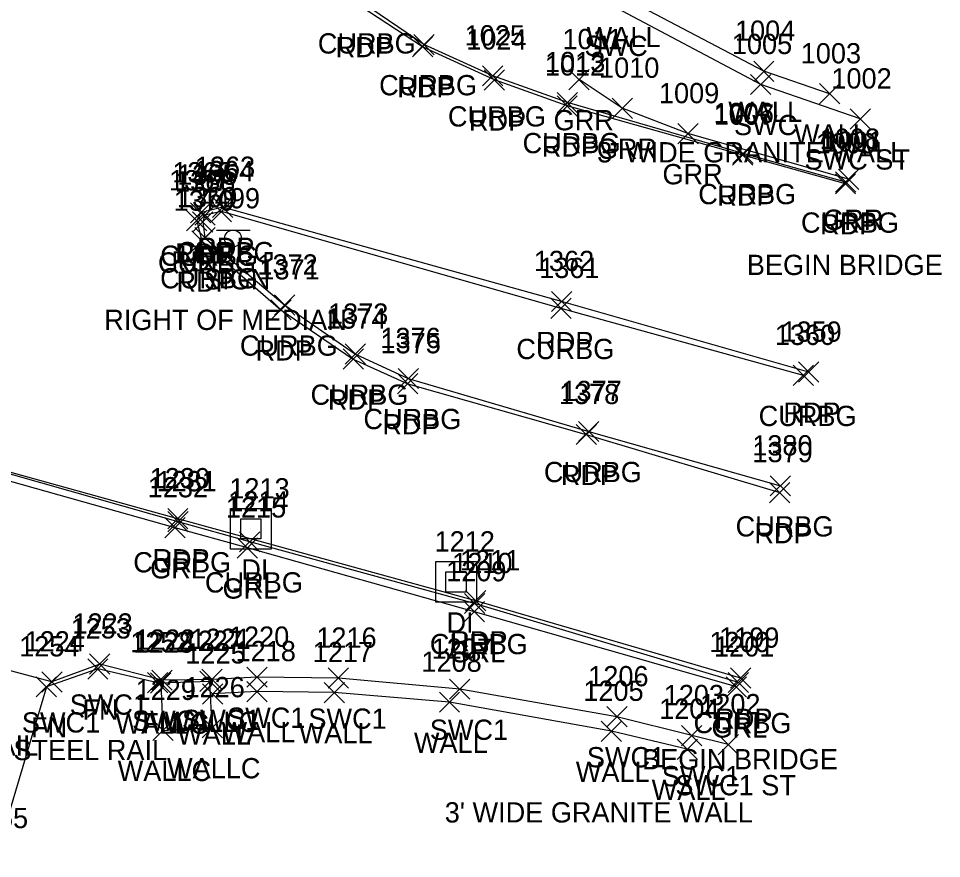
# Model space of a CAD drawing. Extents: x 1690689 to 1696275, y 438760 to 444007.
# Drawn here: x 1693096.4 to 1693187.5, y 438764.8 to 438847.7 of the extents above; entities that cross this region are included whole.
import ezdxf

# ---------------------------------------------------------------- set-up
doc = ezdxf.new("R2010")
doc.units = 0
for name, color, linetype in [('D_A', 7, 'Continuous'), ('D_I', 7, 'Continuous'), ('DS', 7, 'Continuous'), ('L_A', 7, 'Continuous'), ('L_C', 7, 'Continuous'), ('L_I', 7, 'Continuous'), ('L_TIC', 7, 'Continuous'), ('LFNC', 7, 'Continuous'), ('LW', 7, 'Continuous'), ('P_A', 7, 'Continuous'), ('P_C', 7, 'Continuous'), ('P_I', 7, 'Continuous'), ('P_TIC', 7, 'Continuous'), ('PET', 7, 'Continuous'), ('R_A', 7, 'Continuous'), ('R_I', 7, 'Continuous'), ('R_TIC', 7, 'Continuous'), ('RC', 7, 'Continuous'), ('RGR', 7, 'Continuous'), ('RSW', 7, 'Continuous'), ('S_A', 7, 'Continuous'), ('S_C', 7, 'Continuous'), ('S_I', 7, 'Continuous'), ('SSGN', 7, 'Continuous')]:
    doc.layers.add(name, color=color, linetype=linetype)

msp = doc.modelspace()

# ---------------------------------------------------------------- linework, layer by layer
at = {"layer": 'DS'}
for p, q in [((1693117.348, 438799.301), (1693121.348, 438799.301)), ((1693117.348, 438795.301), (1693117.348, 438799.301)), ((1693121.348, 438799.301), (1693121.348, 438795.301)), ((1693118.348, 438796.301), (1693118.348, 438798.301)), ((1693118.348, 438798.301), (1693120.348, 438798.301)), ((1693120.348, 438798.301), (1693120.348, 438796.301)), ((1693119.353, 438797.302), (1693119.353, 438797.302)), ((1693119.353, 438797.302), (1693119.353, 438797.302)), ((1693120.348, 438796.301), (1693118.348, 438796.301)), ((1693121.348, 438795.301), (1693117.348, 438795.301)), ((1693137.59, 438794.063), (1693141.59, 438794.063)), ((1693137.59, 438790.063), (1693137.59, 438794.063)), ((1693141.59, 438794.063), (1693141.59, 438790.063)), ((1693138.59, 438791.063), (1693138.59, 438793.063)), ((1693138.59, 438793.063), (1693140.59, 438793.063)), ((1693140.59, 438793.063), (1693140.59, 438791.063)), ((1693139.595, 438792.065), (1693139.595, 438792.065)), ((1693139.595, 438792.065), (1693139.595, 438792.065)), ((1693140.59, 438791.063), (1693138.59, 438791.063)), ((1693141.59, 438790.063), (1693137.59, 438790.063))]:
    msp.add_line(p, q, dxfattribs=at)
at = {"layer": 'L_TIC'}
for points in [[(1693168.95, 438841.46), (1693170.95, 438843.46)], [(1693170.95, 438841.46), (1693168.95, 438843.46)], [(1693175.439, 438839.232), (1693177.439, 438841.232)], [(1693177.439, 438839.232), (1693175.439, 438841.232)], [(1693103.258, 438782.476), (1693105.258, 438784.476)], [(1693105.258, 438782.476), (1693103.258, 438784.476)], [(1693109.146, 438781.122), (1693111.146, 438783.122)], [(1693111.146, 438781.122), (1693109.146, 438783.122)], [(1693109.459, 438781.081), (1693111.459, 438783.081)], [(1693111.459, 438781.081), (1693109.459, 438783.081)], [(1693114.306, 438781.254), (1693116.306, 438783.254)], [(1693116.306, 438781.254), (1693114.306, 438783.254)], [(1693098.184, 438780.712), (1693100.184, 438782.712)], [(1693100.184, 438780.712), (1693098.184, 438782.712)], [(1693114.581, 438780.013), (1693116.581, 438782.013)], [(1693116.581, 438780.013), (1693114.581, 438782.013)], [(1693118.968, 438780.242), (1693120.968, 438782.242)], [(1693120.968, 438780.242), (1693118.968, 438782.242)], [(1693126.581, 438780.148), (1693128.581, 438782.148)], [(1693128.581, 438780.148), (1693126.581, 438782.148)], [(1693137.944, 438779.198), (1693139.944, 438781.198)], [(1693139.944, 438779.198), (1693137.944, 438781.198)], [(1693109.68, 438776.414), (1693111.68, 438778.414)], [(1693111.68, 438776.414), (1693109.68, 438778.414)], [(1693114.548, 438776.683), (1693116.548, 438778.683)], [(1693116.548, 438776.683), (1693114.548, 438778.683)], [(1693153.914, 438776.324), (1693155.914, 438778.324)], [(1693155.914, 438776.324), (1693153.914, 438778.324)], [(1693161.395, 438774.55), (1693163.395, 438776.55)], [(1693163.395, 438774.55), (1693161.395, 438776.55)]]:
    msp.add_lwpolyline(points, dxfattribs=at)
at = {"layer": 'LFNC'}
msp.add_lwpolyline([(1693110.146, 438782.122), (1693104.258, 438783.476), (1693099.184, 438781.712), (1693094.123, 438764.767)], dxfattribs=at)
at = {"layer": 'LW'}
for points in [[(1693176.439, 438840.232), (1693169.95, 438842.46), (1693155.984, 438849.838), (1693140.477, 438863.014), (1693137.545, 438865.859)], [(1693115.548, 438777.683), (1693115.306, 438782.254), (1693110.459, 438782.081), (1693110.68, 438777.414)], [(1693162.395, 438775.55), (1693154.914, 438777.324), (1693138.944, 438780.198), (1693127.581, 438781.148), (1693119.968, 438781.242), (1693115.581, 438781.013)], [(1693110.68, 438777.414), (1693115.548, 438777.683)]]:
    msp.add_lwpolyline(points, dxfattribs=at)
at = {"layer": 'P_TIC'}
for points in [[(1693135.289, 438843.874), (1693137.289, 438845.874)], [(1693137.289, 438843.874), (1693135.289, 438845.874)], [(1693142.37, 438840.6), (1693144.37, 438842.6)], [(1693144.37, 438840.6), (1693142.37, 438842.6)], [(1693149.55, 438838.032), (1693151.55, 438840.032)], [(1693151.55, 438838.032), (1693149.55, 438840.032)], [(1693166.863, 438833.182), (1693168.863, 438835.182)], [(1693168.863, 438833.182), (1693166.863, 438835.182)], [(1693177.004, 438830.349), (1693179.004, 438832.349)], [(1693179.004, 438830.349), (1693177.004, 438832.349)], [(1693113.392, 438827.488), (1693115.392, 438829.488)], [(1693115.392, 438827.488), (1693113.392, 438829.488)], [(1693115.564, 438828.035), (1693117.564, 438830.035)], [(1693117.564, 438828.035), (1693115.564, 438830.035)], [(1693113.017, 438826.701), (1693115.017, 438828.701)], [(1693115.017, 438826.701), (1693113.017, 438828.701)], [(1693113.519, 438824.694), (1693115.519, 438826.694)], [(1693115.519, 438824.694), (1693113.519, 438826.694)], [(1693149.005, 438818.737), (1693151.005, 438820.737)], [(1693151.005, 438818.737), (1693149.005, 438820.737)], [(1693121.314, 438817.913), (1693123.314, 438819.913)], [(1693123.314, 438817.913), (1693121.314, 438819.913)], [(1693128.453, 438813.06), (1693130.453, 438815.06)], [(1693130.453, 438813.06), (1693128.453, 438815.06)], [(1693173.382, 438811.769), (1693175.382, 438813.769)], [(1693175.382, 438811.769), (1693173.382, 438813.769)], [(1693133.825, 438810.623), (1693135.825, 438812.623)], [(1693135.825, 438810.623), (1693133.825, 438812.623)], [(1693151.428, 438805.614), (1693153.428, 438807.614)], [(1693153.428, 438805.614), (1693151.428, 438807.614)], [(1693170.522, 438799.878), (1693172.522, 438801.878)], [(1693172.522, 438799.878), (1693170.522, 438801.878)], [(1693111.148, 438797.3), (1693113.148, 438799.3)], [(1693113.148, 438797.3), (1693111.148, 438799.3)], [(1693140.529, 438789.204), (1693142.529, 438791.204)], [(1693142.529, 438789.204), (1693140.529, 438791.204)], [(1693166.668, 438781.572), (1693168.668, 438783.572)], [(1693168.668, 438781.572), (1693166.668, 438783.572)]]:
    msp.add_lwpolyline(points, dxfattribs=at)
at = {"layer": 'PET'}
for points in [[(1693178.004, 438831.349), (1693167.863, 438834.182), (1693150.55, 438839.032), (1693143.37, 438841.6), (1693136.289, 438844.874), (1693130.213, 438848.845), (1693123.669, 438855.479), (1693121.208, 438858.853), (1693116.986, 438868.319), (1693115.473, 438875.401), (1693114.995, 438883.117), (1693115.749, 438896.946), (1693117.891, 438910.419), (1693121.336, 438921.379), (1693129.293, 438944.072), (1693138.234, 438969.024), (1693143.649, 438986.671), (1693149.755, 439012.352), (1693154.066, 439032.189), (1693155.341, 439035.219), (1693157.208, 439037.364), (1693158.647, 439037.843), (1693160.136, 439048.773), (1693162.88, 439071.433)], [(1693167.668, 438782.572), (1693141.529, 438790.204), (1693112.148, 438798.3), (1693087.861, 438805.042), (1693057.065, 438813.514), (1693019.123, 438823.554), (1692973.095, 438835.842), (1692924.995, 438847.572), (1692878.498, 438859.294), (1692838.413, 438869.506), (1692796.94, 438879.755), (1692752.346, 438890.066), (1692731.667, 438894.52), (1692658.097, 438910.213), (1692638.647, 438914.4), (1692605.273, 438921.447), (1692561.097, 438930.731), (1692527.614, 438937.28), (1692485.067, 438945.571), (1692435.035, 438955.399)], [(1693174.382, 438812.769), (1693150.005, 438819.737), (1693116.564, 438829.035), (1693114.392, 438828.488), (1693114.017, 438827.701), (1693114.519, 438825.694), (1693122.314, 438818.913), (1693129.453, 438814.06), (1693134.825, 438811.623), (1693152.428, 438806.614), (1693171.522, 438800.878)]]:
    msp.add_lwpolyline(points, dxfattribs=at)
at = {"layer": 'R_TIC'}
for points in [[(1693135.42, 438844.083), (1693137.42, 438846.083)], [(1693137.42, 438844.083), (1693135.42, 438846.083)], [(1693142.206, 438841.003), (1693144.206, 438843.003)], [(1693144.206, 438841.003), (1693142.206, 438843.003)], [(1693150.722, 438840.632), (1693152.722, 438842.632)], [(1693152.722, 438840.632), (1693150.722, 438842.632)], [(1693168.643, 438840.153), (1693170.643, 438842.153)], [(1693170.643, 438840.153), (1693168.643, 438842.153)], [(1693149.571, 438838.369), (1693151.571, 438840.369)], [(1693151.571, 438838.369), (1693149.571, 438840.369)], [(1693154.987, 438837.81), (1693156.987, 438839.81)], [(1693156.987, 438837.81), (1693154.987, 438839.81)], [(1693178.46, 438836.753), (1693180.46, 438838.753)], [(1693180.46, 438836.753), (1693178.46, 438838.753)], [(1693161.46, 438835.3), (1693163.46, 438837.3)], [(1693163.46, 438835.3), (1693161.46, 438837.3)], [(1693166.897, 438833.338), (1693168.897, 438835.338)], [(1693168.897, 438833.338), (1693166.897, 438835.338)], [(1693177.304, 438830.801), (1693179.304, 438832.801)], [(1693179.304, 438830.801), (1693177.304, 438832.801)], [(1693177.03, 438830.525), (1693179.03, 438832.525)], [(1693179.03, 438830.525), (1693177.03, 438832.525)], [(1693113.817, 438827.258), (1693115.817, 438829.258)], [(1693115.817, 438827.258), (1693113.817, 438829.258)], [(1693115.45, 438827.609), (1693117.45, 438829.609)], [(1693117.45, 438827.609), (1693115.45, 438829.609)], [(1693113.605, 438826.585), (1693115.605, 438828.585)], [(1693115.605, 438826.585), (1693113.605, 438828.585)], [(1693113.817, 438825.031), (1693115.817, 438827.031)], [(1693115.817, 438825.031), (1693113.817, 438827.031)], [(1693121.688, 438818.39), (1693123.688, 438820.39)], [(1693123.688, 438818.39), (1693121.688, 438820.39)], [(1693148.954, 438818.051), (1693150.954, 438820.051)], [(1693150.954, 438818.051), (1693148.954, 438820.051)], [(1693128.655, 438813.544), (1693130.655, 438815.544)], [(1693130.655, 438813.544), (1693128.655, 438815.544)], [(1693133.871, 438811.141), (1693135.871, 438813.141)], [(1693135.871, 438811.141), (1693133.871, 438813.141)], [(1693172.853, 438811.445), (1693174.853, 438813.445)], [(1693174.853, 438811.445), (1693172.853, 438813.445)], [(1693151.675, 438805.909), (1693153.675, 438807.909)], [(1693153.675, 438805.909), (1693151.675, 438807.909)], [(1693170.582, 438800.545), (1693172.582, 438802.545)], [(1693172.582, 438800.545), (1693170.582, 438802.545)], [(1693110.87, 438796.408), (1693112.87, 438798.408)], [(1693112.87, 438796.408), (1693110.87, 438798.408)], [(1693111.167, 438797.004), (1693113.167, 438799.004)], [(1693113.167, 438797.004), (1693111.167, 438799.004)], [(1693118.01, 438794.416), (1693120.01, 438796.416)], [(1693120.01, 438794.416), (1693118.01, 438796.416)], [(1693118.239, 438795.018), (1693120.239, 438797.018)], [(1693120.239, 438795.018), (1693118.239, 438797.018)], [(1693140.423, 438788.932), (1693142.423, 438790.932)], [(1693142.423, 438788.932), (1693140.423, 438790.932)], [(1693140.393, 438788.126), (1693142.393, 438790.126)], [(1693142.393, 438788.126), (1693140.393, 438790.126)], [(1693103.442, 438782.963), (1693105.442, 438784.963)], [(1693105.442, 438782.963), (1693103.442, 438784.963)], [(1693118.966, 438781.665), (1693120.966, 438783.665)], [(1693120.966, 438781.665), (1693118.966, 438783.665)], [(1693098.723, 438781.2), (1693100.723, 438783.2)], [(1693100.723, 438781.2), (1693098.723, 438783.2)], [(1693109.594, 438781.372), (1693111.594, 438783.372)], [(1693111.594, 438781.372), (1693109.594, 438783.372)], [(1693114.52, 438781.448), (1693116.52, 438783.448)], [(1693116.52, 438781.448), (1693114.52, 438783.448)], [(1693126.987, 438781.571), (1693128.987, 438783.571)], [(1693128.987, 438781.571), (1693126.987, 438783.571)], [(1693166.437, 438781.138), (1693168.437, 438783.138)], [(1693168.437, 438781.138), (1693166.437, 438783.138)], [(1693138.957, 438780.48), (1693140.957, 438782.48)], [(1693140.957, 438780.48), (1693138.957, 438782.48)], [(1693166.238, 438780.702), (1693168.238, 438782.702)], [(1693168.238, 438780.702), (1693166.238, 438782.702)], [(1693154.452, 438777.766), (1693156.452, 438779.766)], [(1693156.452, 438777.766), (1693154.452, 438779.766)], [(1693161.843, 438775.9), (1693163.843, 438777.9)], [(1693163.843, 438775.9), (1693161.843, 438777.9)], [(1693165.442, 438775.006), (1693167.442, 438777.006)], [(1693167.442, 438775.006), (1693165.442, 438777.006)]]:
    msp.add_lwpolyline(points, dxfattribs=at)
at = {"layer": 'RC'}
for points in [[(1693178.03, 438831.525), (1693167.897, 438834.338), (1693150.571, 438839.369), (1693143.206, 438842.003), (1693136.42, 438845.083), (1693130.372, 438849.203), (1693123.91, 438855.549), (1693121.542, 438858.805), (1693117.19, 438868.367), (1693115.744, 438875.3), (1693115.292, 438883.152), (1693116.004, 438896.823), (1693118.164, 438910.25), (1693121.66, 438921.367), (1693129.619, 438944.142), (1693138.48, 438968.954), (1693143.792, 438986.672), (1693150.084, 439012.322), (1693154.228, 439032.307)], [(1693167.437, 438782.138), (1693141.423, 438789.932), (1693119.239, 438796.018), (1693112.167, 438798.004), (1693087.952, 438804.879), (1693056.947, 438813.294), (1693019.095, 438823.353), (1692973.04, 438835.52), (1692925.287, 438847.097), (1692878.464, 438858.862), (1692838.191, 438869.176), (1692796.465, 438878.899), (1692752.325, 438889.868), (1692731.586, 438894.275), (1692657.894, 438909.925), (1692639.329, 438913.932), (1692605.343, 438921.224), (1692561.269, 438930.492), (1692527.544, 438937.105), (1692485.059, 438945.404), (1692435.016, 438955.146)], [(1693173.853, 438812.445), (1693149.954, 438819.051), (1693116.45, 438828.609), (1693114.817, 438828.258), (1693114.605, 438827.585), (1693114.817, 438826.031), (1693122.688, 438819.39), (1693129.655, 438814.544), (1693134.871, 438812.141), (1693152.675, 438806.909), (1693171.582, 438801.545)]]:
    msp.add_lwpolyline(points, dxfattribs=at)
at = {"layer": 'RGR'}
for points in [[(1693178.304, 438831.801), (1693162.46, 438836.3), (1693155.987, 438838.81), (1693151.722, 438841.632)], [(1693167.238, 438781.702), (1693141.393, 438789.126), (1693119.01, 438795.416), (1693111.87, 438797.408), (1693087.677, 438804.202), (1693056.506, 438812.558), (1693018.729, 438822.68), (1693002.536, 438826.801), (1692985.216, 438829.713), (1692972.918, 438830.395)]]:
    msp.add_lwpolyline(points, dxfattribs=at)
at = {"layer": 'RSW'}
for points in [[(1693179.46, 438837.753), (1693169.643, 438841.153), (1693154.894, 438848.962), (1693136.64, 438864.808), (1693132.979, 438868.262), (1693130.108, 438872.39)], [(1693166.442, 438776.006), (1693162.843, 438776.9), (1693155.452, 438778.766), (1693139.957, 438781.48), (1693127.987, 438782.571), (1693119.966, 438782.665), (1693115.52, 438782.448), (1693110.594, 438782.372), (1693104.442, 438783.963), (1693099.723, 438782.2), (1693091.521, 438784.365), (1693085.438, 438793.615), (1693061.823, 438800.984), (1693023.099, 438811.357), (1693012.023, 438814.042), (1693010.681, 438813.289), (1692996.009, 438816.977), (1692970.829, 438823.581), (1692966.836, 438812.173)]]:
    msp.add_lwpolyline(points, dxfattribs=at)
at = {"layer": 'SSGN'}
for p, q in [((1693115.945, 438826.782), (1693119.278, 438826.782)), ((1693117.592, 438825.948), (1693117.592, 438825.948))]:
    msp.add_line(p, q, dxfattribs=at)
msp.add_circle((1693117.592, 438825.948), 0.833, dxfattribs=at)

# ---------------------------------------------------------------- texts
at = {"layer": 'D_A'}
for p in [(1693118.408, 438792.302), (1693138.65, 438787.065)]:
    msp.add_text('DI', height=2, dxfattribs=at).set_placement(p)
at = {"layer": 'D_I'}
for s, p in [('1213', (1693117.227, 438800.302)), ('1212', (1693137.469, 438795.065))]:
    msp.add_text(s, height=2, dxfattribs=at).set_placement(p)
at = {"layer": 'L_A'}
for s, p in [('WALL', (1693152.472, 438844.838)), ('WALL', (1693166.438, 438837.46)), ('WALL', (1693172.927, 438835.232)), ('FN', (1693102.739, 438778.476)), ('WALLC', (1693105.995, 438777.081)), ('FN', (1693108.626, 438777.122)), ('WALLC', (1693110.842, 438777.254)), ('FN', (1693097.665, 438776.712)), ('WALL', (1693116.456, 438776.242)), ('WALL', (1693112.069, 438776.013)), ('WALL', (1693124.069, 438776.148)), ('WALL', (1693135.432, 438775.198)), ('WALLC', (1693111.084, 438772.683)), ('WALLC', (1693106.215, 438772.414)), ('WALL', (1693151.402, 438772.324)), ('WALL', (1693158.883, 438770.55))]:
    msp.add_text(s, height=2, dxfattribs=at).set_placement(p)
at = {"layer": 'L_C'}
for s, p in [("3' WIDE GRANITE WALL", (1693153.509, 438833.46)), ('STEEL RAIL', (1693083.211, 438774.92)), ('STEEL RAIL', (1693095.928, 438774.476)), ("3' WIDE GRANITE WALL", (1693138.473, 438768.324))]:
    msp.add_text(s, height=2, dxfattribs=at).set_placement(p)
at = {"layer": 'L_I'}
for s, p in [('1004', (1693167.1, 438845.46)), ('1003', (1693173.588, 438843.232)), ('1253', (1693101.566, 438786.476)), ('1227', (1693112.613, 438785.254)), ('1254', (1693096.492, 438784.712)), ('1252', (1693107.453, 438785.122)), ('1228', (1693107.766, 438785.081)), ('1225', (1693112.888, 438784.013)), ('1218', (1693117.842, 438784.242)), ('1217', (1693125.455, 438784.148)), ('1208', (1693136.172, 438783.198)), ('1229', (1693107.979, 438780.414)), ('1226', (1693112.8, 438780.683)), ('1205', (1693152.142, 438780.324)), ('1204', (1693159.623, 438778.55)), ('1255', (1693091.43, 438767.767))]:
    msp.add_text(s, height=2, dxfattribs=at).set_placement(p)
at = {"layer": 'P_A'}
for p in [(1693127.702, 438843.845), (1693133.777, 438839.874), (1693140.859, 438836.6), (1693148.038, 438834.032), (1693165.351, 438829.182), (1693175.492, 438826.349), (1693114.052, 438824.035), (1693111.505, 438822.701), (1693111.88, 438823.488), (1693112.008, 438820.694), (1693147.493, 438814.737), (1693119.803, 438813.913), (1693126.941, 438809.06), (1693171.87, 438807.769), (1693132.313, 438806.623), (1693149.916, 438801.614), (1693169.011, 438795.878), (1693109.636, 438793.3), (1693139.017, 438785.204), (1693165.156, 438777.572)]:
    msp.add_text('RDP', height=2, dxfattribs=at).set_placement(p)
at = {"layer": 'P_C'}
for p in [(1693168.272, 438822.349), (1693157.936, 438773.572)]:
    msp.add_text('BEGIN BRIDGE', height=2, dxfattribs=at).set_placement(p)
at = {"layer": 'P_I'}
for s, p in [('1024', (1693140.599, 438844.6)), ('1012', (1693148.345, 438842.032)), ('1007', (1693165.013, 438837.182)), ('1000', (1693175.067, 438834.349)), ('1363', (1693113.824, 438832.035)), ('1366', (1693111.597, 438831.488)), ('1367', (1693111.277, 438830.701)), ('1370', (1693111.74, 438828.694)), ('1362', (1693147.265, 438822.737)), ('1371', (1693120.188, 438821.913)), ('1374', (1693126.76, 438817.06)), ('1359', (1693171.681, 438815.769)), ('1375', (1693132.132, 438814.623)), ('1378', (1693149.735, 438809.614)), ('1379', (1693168.822, 438803.878)), ('1230', (1693109.369, 438801.3)), ('1211', (1693139.97, 438793.204)), ('1199', (1693165.534, 438785.572))]:
    msp.add_text(s, height=2, dxfattribs=at).set_placement(p)
at = {"layer": 'R_A'}
for s, p in [('CURBG', (1693125.955, 438844.203)), ('SWC', (1693152.256, 438843.962)), ('CURBG', (1693132.003, 438840.083)), ('CURBG', (1693138.789, 438837.003)), ('GRR', (1693149.21, 438836.632)), ('SWC', (1693167.006, 438836.153)), ('CURBG', (1693146.154, 438834.369)), ('GRR', (1693153.475, 438833.81)), ('SWC ST', (1693173.956, 438832.753)), ('GRR', (1693159.949, 438831.3)), ('CURBG', (1693163.48, 438829.338)), ('CURBG', (1693173.613, 438826.525)), ('GRR', (1693175.793, 438826.801)), ('CURBG', (1693112.033, 438823.609)), ('CURBG', (1693110.187, 438822.585)), ('CURBG', (1693110.4, 438823.258)), ('CURBG', (1693110.4, 438821.031)), ('CURBG', (1693118.27, 438814.39)), ('CURBG', (1693145.537, 438814.051)), ('CURBG', (1693125.237, 438809.544)), ('CURBG', (1693130.454, 438807.141)), ('CURBG', (1693169.436, 438807.445)), ('CURBG', (1693148.257, 438801.909)), ('CURBG', (1693167.165, 438796.545)), ('CURBG', (1693107.75, 438793.004)), ('GRL', (1693109.413, 438792.408)), ('CURBG', (1693114.821, 438791.018)), ('GRL', (1693116.553, 438790.416)), ('CURBG', (1693137.005, 438784.932)), ('GRL', (1693138.937, 438784.126)), ('SWC1', (1693101.481, 438778.963)), ('SWC1', (1693096.762, 438777.2)), ('SWC1', (1693107.633, 438777.372)), ('SWC1', (1693112.56, 438777.448)), ('SWC1', (1693117.005, 438777.665)), ('SWC1', (1693125.026, 438777.571)), ('CURBG', (1693163.02, 438777.138)), ('SWC1', (1693136.997, 438776.48)), ('GRL', (1693164.781, 438776.702)), ('SWC1', (1693152.492, 438773.766)), ('SWC1', (1693159.883, 438771.9)), ('SWC1 ST', (1693161.222, 438771.006))]:
    msp.add_text(s, height=2, dxfattribs=at).set_placement(p)
at = {"layer": 'R_I'}
for s, p in [('1025', (1693140.434, 438845.003)), ('1011', (1693150.084, 438844.632)), ('1005', (1693166.793, 438844.153)), ('1013', (1693148.367, 438842.369)), ('1010', (1693153.696, 438841.81)), ('1002', (1693176.61, 438840.753)), ('1009', (1693159.602, 438839.3)), ('1006', (1693164.992, 438837.338)), ('1008', (1693175.454, 438834.801)), ('1001', (1693175.747, 438834.525)), ('1365', (1693112.077, 438831.258)), ('1364', (1693113.71, 438831.609)), ('1368', (1693111.865, 438830.585)), ('1369', (1693112.069, 438829.031)), ('1372', (1693119.995, 438822.39)), ('1361', (1693147.781, 438822.051)), ('1373', (1693126.962, 438817.544)), ('1360', (1693171.027, 438815.445)), ('1376', (1693132.123, 438815.141)), ('1377', (1693149.982, 438809.909)), ('1380', (1693168.803, 438804.545)), ('1231', (1693110.041, 438801.004)), ('1232', (1693109.177, 438800.408)), ('1214', (1693117.113, 438799.018)), ('1215', (1693116.884, 438798.416)), ('1210', (1693139.21, 438792.932)), ('1209', (1693138.614, 438792.126)), ('1223', (1693101.749, 438786.963)), ('1222', (1693107.901, 438785.372)), ('1221', (1693113.394, 438785.448)), ('1220', (1693117.186, 438785.665)), ('1216', (1693125.806, 438785.571)), ('1224', (1693097.03, 438785.2)), ('1207', (1693137.186, 438784.48)), ('1200', (1693164.579, 438785.138)), ('1201', (1693165.033, 438784.702)), ('1206', (1693152.626, 438781.766)), ('1203', (1693160.072, 438779.9)), ('1202', (1693163.671, 438779.006))]:
    msp.add_text(s, height=2, dxfattribs=at).set_placement(p)
at = {"layer": 'S_A'}
msp.add_text('SIGN', height=2, dxfattribs=at).set_placement((1693114.73, 438820.928))
at = {"layer": 'S_C'}
msp.add_text('RIGHT OF MEDIAN', height=2, dxfattribs=at).set_placement((1693104.887, 438816.928))
at = {"layer": 'S_I'}
msp.add_text('4499', height=2, dxfattribs=at).set_placement((1693114.305, 438828.928))

doc.saveas('drawing.dxf')
